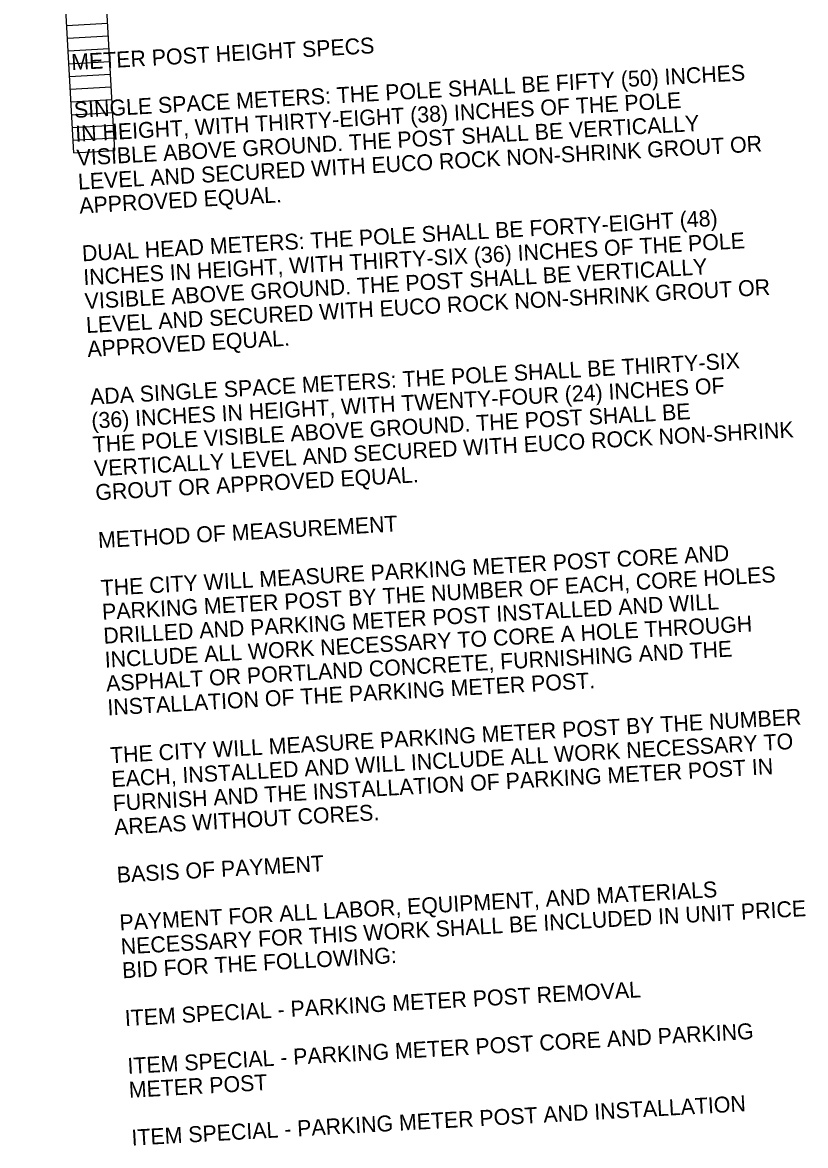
# Model space of a CAD drawing. Extents: x 1822280 to 1825263, y 710141 to 711534.
# Drawn here: x 1824483.3 to 1824826.9, y 710363 to 710855.6 of the extents above; entities that cross this region are included whole.
import ezdxf

# ---------------------------------------------------------------- set-up
doc = ezdxf.new("R2010")
doc.units = 0
doc.layers.add('PM_P_Text', color=7, linetype='Continuous')
doc.layers.add('SC_Scratch1', color=7, linetype='Continuous')

msp = doc.modelspace()

# ---------------------------------------------------------------- linework, layer by layer
at = {"layer": 'SC_Scratch1'}
for p, q in [((1824505.83, 710798.41), (1824483.28, 711200.98)), ((1824523.8, 710799.42), (1824501.25, 711201.98)), ((1824502.7, 710854.32), (1824520.67, 710855.33)), ((1824503.01, 710848.73), (1824520.98, 710849.74)), ((1824503.33, 710843.14), (1824521.3, 710844.15)), ((1824503.64, 710837.55), (1824521.61, 710838.55)), ((1824503.95, 710831.96), (1824521.92, 710832.96)), ((1824504.27, 710826.36), (1824522.24, 710827.37)), ((1824504.58, 710820.77), (1824522.55, 710821.78)), ((1824504.89, 710815.18), (1824522.86, 710816.19)), ((1824505.2, 710809.59), (1824523.18, 710810.6)), ((1824505.52, 710804), (1824523.49, 710805.01)), ((1824505.83, 710798.41), (1824523.8, 710799.42))]:
    msp.add_line(p, q, dxfattribs=at)

# ---------------------------------------------------------------- texts
at = {"layer": 'PM_P_Text'}
for s, p in [('METER POST HEIGHT SPECS', (1824504.91, 710834.71)), ('SINGLE SPACE METERS: THE POLE SHALL BE FIFTY (50) INCHES ', (1824506.08, 710813.75)), ('IN HEIGHT, WITH THIRTY-EIGHT (38) INCHES OF THE POLE ', (1824506.67, 710803.26)), ('VISIBLE ABOVE GROUND. THE POST SHALL BE VERTICALLY ', (1824507.26, 710792.78)), ('LEVEL AND SECURED WITH EUCO ROCK NON-SHRINK GROUT OR ', (1824507.84, 710782.29)), ('APPROVED EQUAL.  ', (1824508.43, 710771.81)), ('DUAL HEAD METERS: THE POLE SHALL BE FORTY-EIGHT (48) ', (1824509.61, 710750.84)), ('INCHES IN HEIGHT, WITH THIRTY-SIX (36) INCHES OF THE POLE ', (1824510.19, 710740.36)), ('VISIBLE ABOVE GROUND. THE POST SHALL BE VERTICALLY ', (1824510.78, 710729.88)), ('LEVEL AND SECURED WITH EUCO ROCK NON-SHRINK GROUT OR ', (1824511.37, 710719.39)), ('APPROVED EQUAL.  ', (1824511.95, 710708.91)), ('ADA SINGLE SPACE METERS: THE POLE SHALL BE THIRTY-SIX ', (1824513.13, 710687.94)), ('(36) INCHES IN HEIGHT, WITH TWENTY-FOUR (24) INCHES OF ', (1824513.72, 710677.46)), ('THE POLE VISIBLE ABOVE GROUND. THE POST SHALL BE ', (1824514.3, 710666.98)), ('VERTICALLY LEVEL AND SECURED WITH EUCO ROCK NON-SHRINK ', (1824514.89, 710656.49)), ('GROUT OR APPROVED EQUAL.', (1824515.48, 710646.01)), ('METHOD OF MEASUREMENT', (1824516.65, 710625.04)), ('THE CITY WILL MEASURE PARKING METER POST CORE AND ', (1824517.83, 710604.07)), ('PARKING METER POST BY THE NUMBER OF EACH, CORE HOLES ', (1824518.41, 710593.59)), ('DRILLED AND PARKING METER POST INSTALLED AND WILL ', (1824519, 710583.11)), ('INCLUDE ALL WORK NECESSARY TO CORE A HOLE THROUGH ', (1824519.59, 710572.62)), ('ASPHALT OR PORTLAND CONCRETE, FURNISHING AND THE ', (1824520.17, 710562.14)), ('INSTALLATION OF THE PARKING METER POST.', (1824520.76, 710551.66)), ('THE CITY WILL MEASURE PARKING METER POST BY THE NUMBER ', (1824521.94, 710530.69)), ('EACH, INSTALLED AND WILL INCLUDE ALL WORK NECESSARY TO ', (1824522.52, 710520.21)), ('FURNISH AND THE INSTALLATION OF PARKING METER POST IN ', (1824523.11, 710509.72)), ('AREAS WITHOUT CORES.', (1824523.7, 710499.24)), ('BASIS OF PAYMENT', (1824524.87, 710478.27)), ('PAYMENT FOR ALL LABOR, EQUIPMENT, AND MATERIALS ', (1824526.05, 710457.3)), ('NECESSARY FOR THIS WORK SHALL BE INCLUDED IN UNIT PRICE ', (1824526.63, 710446.82)), ('BID FOR THE FOLLOWING:', (1824527.22, 710436.34)), ('ITEM SPECIAL - PARKING METER POST REMOVAL', (1824528.4, 710415.37)), ('ITEM SPECIAL - PARKING METER POST CORE AND PARKING ', (1824529.57, 710394.4)), ('METER POST', (1824530.16, 710383.92)), ('ITEM SPECIAL - PARKING METER POST AND INSTALLATION', (1824531.33, 710362.95))]:
    msp.add_text(s, height=7, rotation=3.2059, dxfattribs=at).set_placement(p)

doc.saveas('drawing.dxf')
